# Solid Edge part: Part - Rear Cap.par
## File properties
Author: hhakima
Template: Normal.par
Last saved by: hhakima
Revision: 21
Application: Solid Edge
Density: 2712.000 kg/m^3
Accuracy: 0.990
Material: Aluminum, 6061-T6
Face Style: Aluminum
Fill Style: ANSI38(Aluminum)
Virtual Style: Polished aluminum
Coef. of Thermal Exp: 2.3e-05
Thermal Conductivity: 180.0
Specific Heat: 920.0
Modulus of Elasticity: 68947570000.0
Poission's Ratio: 0.33
Yield Stress: 275790280.0
Ultimate Stress: 310264065.0
Elongation: 0.0
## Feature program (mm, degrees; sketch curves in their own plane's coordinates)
sketch for "unnamed Protrusion 1" plane through (0, 0, 0) normal (0, -1, 0) x-axis (1, 0, 0)
  line (42.2517, 30.6615) -> (98.2517, 30.6615)
  line (98.2517, 30.6615) -> (98.2517, 67.6615)
  line (98.2517, 67.6615) -> (42.2517, 67.6615)
  line (42.2517, 67.6615) -> (42.2517, 30.6615)
extrude "unnamed Protrusion 1" add finite 2 along +normal
sketch for "ExtrudedProtrusion_2" #1 plane through (63.7517, -2, 49.1615) normal (0, -1, 0) x-axis (1, 0, 0)
  line (-21.5, -13.5) -> (-21.5, -18.5)
  line (-21.5, -18.5) -> (-26.5, -18.5)
  line (-26.5, -18.5) -> (-26.5, -13.5)
  line (-26.5, -13.5) -> (-21.5, -13.5)
sketch for "ExtrudedProtrusion_2" #2 plane through (63.7517, -2, 49.1615) normal (0, -1, 0) x-axis (1, 0, 0)
  line (34.5, -13.5) -> (34.5, -18.5)
  line (34.5, -18.5) -> (39.5, -18.5)
  line (39.5, -18.5) -> (39.5, -13.5)
  line (39.5, -13.5) -> (34.5, -13.5)
sketch for "ExtrudedProtrusion_2" #3 plane through (63.7517, -2, 49.1615) normal (0, -1, 0) x-axis (1, 0, 0)
sketch for "ExtrudedProtrusion_2" #4 plane through (63.7517, -2, 49.1615) normal (0, -1, 0) x-axis (1, 0, 0)
  line (24.5, 18.5) -> (29.5, 18.5)
  line (29.5, 18.5) -> (29.5, 23.5)
  line (29.5, 23.5) -> (24.5, 23.5)
  line (24.5, 23.5) -> (24.5, 18.5)
  dimension (linear) = 24.5
extrude "ExtrudedProtrusion_2" add finite 2 along -normal
sketch for "unnamed Hole 1" plane through (63.7517, -2, 49.1615) normal (0, -1, 0) x-axis (1, 0, 0)
  hole centre (27, 21) bore radius 0.7835
hole "unnamed Hole 1" through
sketch for "unnamed Hole 2" plane through (63.7517, -2, 49.1615) normal (0, -1, 0) x-axis (1, 0, 0)
  hole centre (37, -16) bore radius 0.7835
hole "unnamed Hole 2" through
sketch for "unnamed Hole 3" plane through (63.7517, -2, 49.1615) normal (0, -1, 0) x-axis (1, 0, 0)
  hole centre (-24, -16) bore radius 0.7835
  dimension (linear) = 24
  dimension (linear) = 24
hole "unnamed Hole 3" through
sketch for "unnamed Hole 4" plane through (63.7517, -2, 49.1615) normal (0, -1, 0) x-axis (1, 0, 0)
hole "unnamed Hole 4" through
pattern "unnamed Pattern 1" of "unnamed Hole 1", "unnamed Hole 2", "unnamed Hole 3", "unnamed Hole 4"
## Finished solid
Body 1: solid body, 22 faces, 56 edges, 32 vertices.
  Faces by surface: plane 18, cylinder 4
  Edges by curve: line 48, circle 8
Bounding box of the edges (mm): 66.000 x 2.000 x 42.000, from (37.2517, -2, 30.6615) to (103.2517, 0, 72.6615).
Cylindrical faces by radius (mm): R0.7835 x4
Planar faces by outward normal: +x 4, +y 1, +z 7, -x 4, -y 1, -z 1
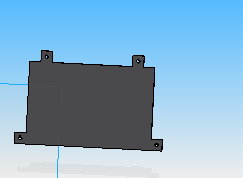
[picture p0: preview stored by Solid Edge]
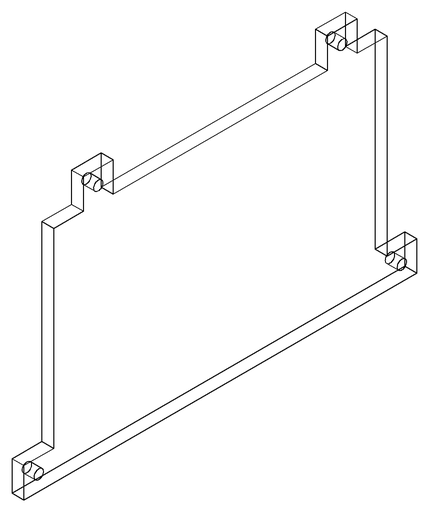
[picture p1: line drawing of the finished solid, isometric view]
